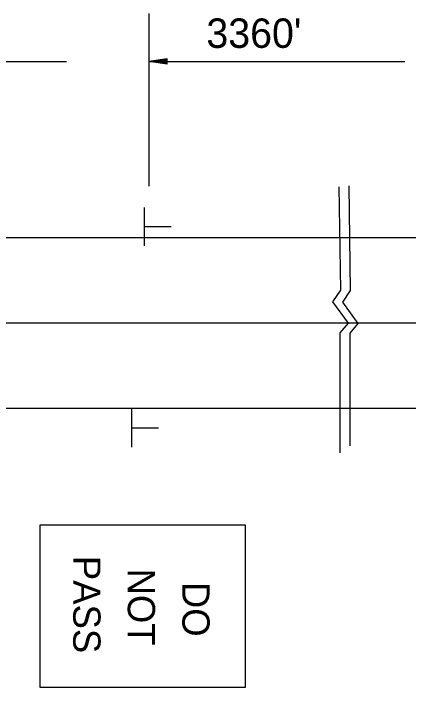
# Model space of a CAD drawing. Extents: x 1374897 to 1375063, y 381144 to 381251.
# Drawn here: x 1374936.76 to 1374944.82, y 381210.53 to 381224.27 of the extents above; entities that cross this region are included whole.
import ezdxf

# ---------------------------------------------------------------- set-up
doc = ezdxf.new("R2010")
doc.units = 0
doc.layers.add('Default', color=7, linetype='Continuous')

msp = doc.modelspace()

# ---------------------------------------------------------------- linework, layer by layer
at = {"layer": 'Default'}
for p, q in [((1374939.523, 381224.27), (1374939.523, 381220.75)), ((1374932.622, 381223.291), (1374937.841, 381223.291)), ((1374939.898, 381223.348), (1374939.523, 381223.291)), ((1374939.523, 381223.291), (1374944.741, 381223.291)), ((1374939.898, 381223.235), (1374939.523, 381223.291)), ((1374939.898, 381223.338), (1374939.585, 381223.291)), ((1374939.898, 381223.244), (1374939.585, 381223.291)), ((1374939.898, 381223.329), (1374939.65, 381223.291)), ((1374939.898, 381223.254), (1374939.65, 381223.291)), ((1374939.898, 381223.319), (1374939.712, 381223.291)), ((1374939.898, 381223.263), (1374939.712, 381223.291)), ((1374939.898, 381223.31), (1374939.776, 381223.291)), ((1374939.898, 381223.273), (1374939.776, 381223.291)), ((1374939.898, 381223.3), (1374939.838, 381223.291)), ((1374939.898, 381223.283), (1374939.838, 381223.291)), ((1374939.898, 381223.235), (1374939.898, 381223.348)), ((1374939.432, 381219.536), (1374939.432, 381220.318)), ((1374939.443, 381219.925), (1374939.977, 381219.925)), ((1374935.327, 381219.7), (1374942.721, 381219.7)), ((1374942.721, 381219.7), (1374948.918, 381219.7)), ((1374935.327, 381217.961), (1374942.767, 381217.961)), ((1374942.767, 381217.961), (1374948.885, 381217.961)), ((1374935.327, 381216.223), (1374942.813, 381216.223)), ((1374942.813, 381216.223), (1374948.851, 381216.223)), ((1374939.174, 381215.431), (1374939.174, 381216.213)), ((1374939.185, 381215.82), (1374939.719, 381215.82))]:
    msp.add_line(p, q, dxfattribs=at)
for points in [[(1374943.599, 381220.755), (1374943.632, 381218.624), (1374943.469, 381218.382), (1374943.786, 381217.95), (1374943.619, 381217.75), (1374943.619, 381215.453)], [(1374943.4, 381220.736), (1374943.432, 381218.632), (1374943.27, 381218.391), (1374943.586, 381217.958), (1374943.419, 381217.758), (1374943.419, 381215.312)]]:
    msp.add_lwpolyline(points, dxfattribs=at)
msp.add_lwpolyline([(1374941.488, 381210.528), (1374937.306, 381210.528), (1374937.306, 381213.846), (1374941.488, 381213.846)], close=True, dxfattribs=at)

# ---------------------------------------------------------------- texts
msp.add_text("3360'", height=0.6, dxfattribs=at).set_placement((1374940.696, 381223.569))
for s, p in [('PASS', (1374937.98, 381213.213)), ('NOT', (1374939.093, 381212.954)), ('DO', (1374940.206, 381212.682))]:
    msp.add_text(s, height=0.5566, rotation=270, dxfattribs=at).set_placement(p)

doc.saveas('drawing.dxf')
